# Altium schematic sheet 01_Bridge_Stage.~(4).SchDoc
size A4; SheetNumber: 1; SheetTotal: 3
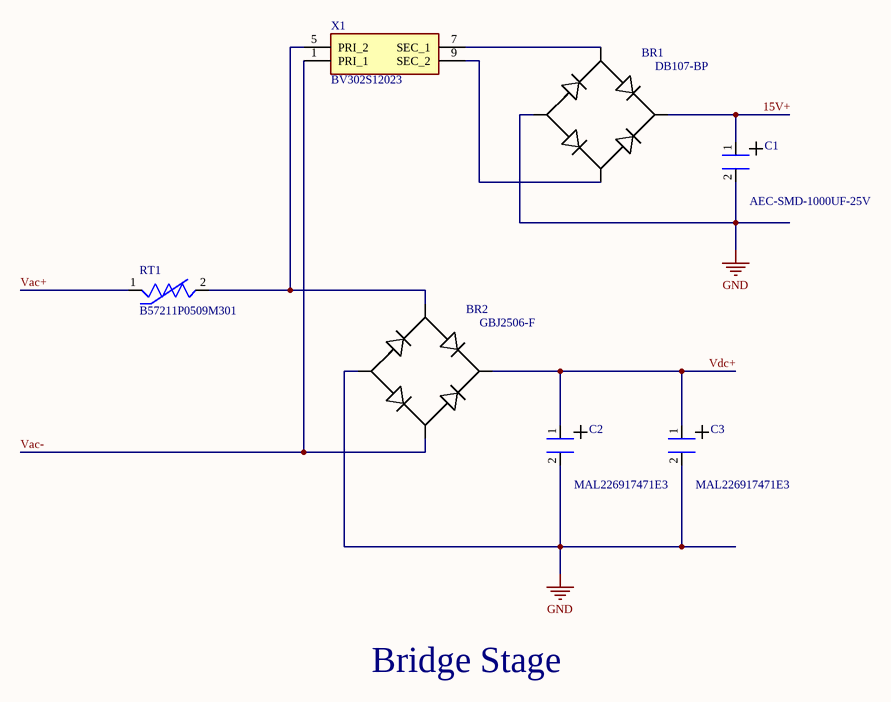
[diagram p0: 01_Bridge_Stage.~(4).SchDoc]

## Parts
BR1  DB107-BP  [898_DB107-BP]
BR2  GBJ2506-F  [996_GBJ_1]
C1  AEC-SMD-1000UF-25V  [098_AEC-SMD-1000UF-25V]
C2  MAL226917471E3  [099_MAL226917471E3]
C3  MAL226917471E3  [099_MAL226917471E3]
RT1  B57211P0509M301  [307_THRMRB750W80L1300T600H2000]
X1  BV302S12023  [899_BV302S12023]

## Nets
GND: BR1.2 BR2.4 C1.2 C2.2 C3.2
15V+: BR1.1 C1.1
Vac+: RT1.1
Vac-: BR2.3 X1.1(PRI_1)
Vdc+: BR2.1 C2.1 C3.1
NetBR1_3: BR1.3 X1.7(SEC_1)
NetBR1_4: BR1.4 X1.9(SEC_2)
NetBR2_2: BR2.2 RT1.2 X1.5(PRI_2)

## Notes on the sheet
- Bridge Stage

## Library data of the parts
BR1 = DB107-BP: Description; Manufacturer_Name: MCC
BR2 = GBJ2506-F: Bridge Rectifier; Manufacturer_Name: Diodes Incorporated
C1 = AEC-SMD-1000UF-25V: 1000 µF, 25 V polarized aluminum electrolytic capacitor, SMD V-chip package, Ø10 mm body, approx. 10.5 mm height, 105 °C rated.
C2 C3 = MAL226917471E3: 470 µF, 450 V polarized aluminum electrolytic capacitor, snap-in THT, Ø35 mm body, 10 mm lead spacing, 105 °C rated.
RT1 = B57211P0509M301: Inrush Current Limiter 5 Ohms Â±20% 5 A 0.512 (13.00mm); MF: EPCOS
X1 = BV302S12023: 2.3VA Encapsulated Transformer 50/60Hz; Manufacturer_Name: Zettler Group; Geometry.Height: 29.8mm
